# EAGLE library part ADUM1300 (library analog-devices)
Triple-Channel Digital Isolators Source: http://www.analog.com/static/imported-files/data_sheets/ADuM1300_1301.pdf
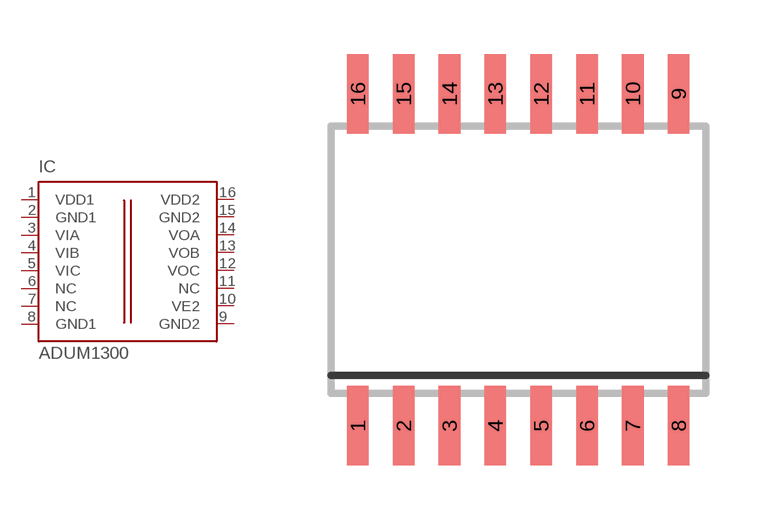
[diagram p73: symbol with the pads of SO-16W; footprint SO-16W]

Designator prefix IC

## ADUM1300 (MPN: ADUM1300ARWZ; OC_FARNELL: 1465621; OC_NEWARK: 19M8751)  [SO-16W]
1  VDD1  in
2  GND1  in
3  VIA  in
4  VIB  in
5  VIC  in
6  NC  nc
7  NC  nc
8  GND1  in
9  GND2  in
10  VE2  in
11  NC  nc
12  VOC  hiz
13  VOB  hiz
14  VOA  hiz
15  GND2  in
16  VDD2  in

## Footprint SO-16W (pad centres in mm)
16-Lead (Wide Body) Small Outline Package (R-16) Source: http://www.analog.com/UploadedFiles/Data_Sheets/409317160AD421_c.pdf
smd 0.6 x 2.2: 1 -4.445,-4.6; 2 -3.175,-4.6; 3 -1.905,-4.6; 4 -0.635,-4.6; 5 0.635,-4.6; 6 1.905,-4.6; 7 3.175,-4.6; 8 4.445,-4.6; 9 4.445,4.6; 10 3.175,4.6; 11 1.905,4.6; 12 0.635,4.6; 13 -0.635,4.6; 14 -1.905,4.6; 15 -3.175,4.6; 16 -4.445,4.6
